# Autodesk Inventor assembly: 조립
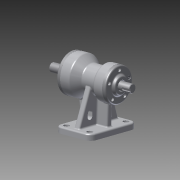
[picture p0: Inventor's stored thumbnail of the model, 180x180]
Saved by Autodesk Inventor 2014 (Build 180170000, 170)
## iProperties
Created: 2015-08
Part Number: 조립
Document SubType Name: Assembly
Designer: Owner
Author: Owner
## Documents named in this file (10)
- C:\Documents and Settings\Owner\바탕 화면\450805V1005\조립.iam
- C:\Documents and Settings\Owner\바탕 화면\450805V1005\축.ipt
- C:\Documents and Settings\Owner\바탕 화면\450805V1005\베어링 6203.ipt
- C:\Documents and Settings\Owner\바탕 화면\450805V1005\베어링 6205.ipt
- C:\Documents and Settings\Owner\바탕 화면\450805V1005\뒤커버.ipt
- C:\Documents and Settings\Owner\바탕 화면\450805V1005\앞커버.ipt
- C:\Documents and Settings\Owner\바탕 화면\450805V1005\본체.ipt
- C:\Documents and Settings\Owner\바탕 화면\450805V1005\오일실 .ipt
- 오일실 .ipt
- C:\Documents and Settings\Owner\바탕 화면\450805V1005\M4x0.5.ipt
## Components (2 placed, 1 different names)
1. M4x0.5:1
2. M4x0.5:2
